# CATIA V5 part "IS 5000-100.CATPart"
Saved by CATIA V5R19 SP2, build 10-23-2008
Part number: IS 5000-100
Bounding box of the stored display mesh (mm): x -59.975 to 59.975, y -59.975 to 59.975, z 0 to 340
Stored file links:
  C:\Users\Bora\Desktop\3D Katı model\IS serisi\IS 5000\IS 5000-100.CATPart
  C:\Program Files\Dassault Systemes\B19\intel_a\reffiles\standard\MetricThickPitch.txt
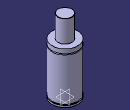
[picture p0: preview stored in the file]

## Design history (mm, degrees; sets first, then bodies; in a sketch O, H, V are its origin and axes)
Body1 (main body)
  Sketch1 on yz-plane, origin (0, 0, 0), H (0, 1, 0), V (0, 0, 1)
    point P1 (60, 217)
    point P2 (60, 212)
    point P5 (32.5, 339)
    point P7 (32.5, 339)
    point P12 (60, 212)
    point P13 (60, 217)
    arc A1 centre (60, 214.5) radius 2.5 from (60, 217) to (60, 212) ccw
    line L1 (60, 0) -> (60, 8)
    line L2 (32.5, 339) -> (32.5, 237)
    arc A2 centre (31.5, 339) radius 1 from (32.5, 339) to (31.5, 340) ccw
    line L3 (56, 13) -> (56, 8)
    line L4 (60, 13) -> (60, 212)
    line L5 (60, 217) -> (60, 237)
    line L6 (31.5, 340) -> (0, 340)
    point P15 (0, 340)
    line L7 (32.5, 237) -> (60, 237)
    line L8 (0, 0) -> (60, 0)
    line L9 (56, 8) -> (60, 8)
    line L10 (56, 13) -> (60, 13)
    coincidence: P15 V, P1 P13, P2 P12, P5 P7
    tangency: L6 A2
    horizontal: L7 H, L8 H, L9 H, L10 H
  Shaft1: profile Sketch1, axis Sketch1.V, angle 360
  Sketch2 on face of Shaft1 from Sketch1.L8, origin (0, 0, 0), H (1, 0, 0), V (0, -1, 0)
    point P1 (40, 0)
    distance P1 V = 40
  Hole1: placed by Sketch2, at (40, 0, 0) direction (0, 0, 1), diameter 8.376, depth 16, threaded "M10", thread diameter 10, thread depth 16, pitch 1.5
  CircPattern1: of Hole1, instances 4, angular step 90, axis from xy-plane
